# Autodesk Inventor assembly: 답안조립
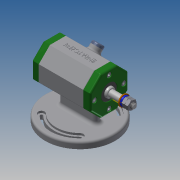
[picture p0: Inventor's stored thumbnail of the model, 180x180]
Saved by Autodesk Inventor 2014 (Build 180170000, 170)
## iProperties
Created: 2017-06
Part Number: 답안조립
Document SubType Name: Assembly
Designer: SCD-A14
Author: SCD-A14
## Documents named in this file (14)
- C:\Users\SCD-A14\Desktop\470607V1017\470607V1017\답안조립.iam
- C:\Users\SCD-A14\Desktop\470607V1017\470607V1017\V벨트풀리.ipt
- C:\Users\SCD-A14\Desktop\470607V1017\470607V1017\고무캡.ipt
- C:\Users\SCD-A14\Desktop\470607V1017\470607V1017\너트 M 8.ipt
- C:\Users\SCD-A14\Desktop\470607V1017\470607V1017\뒤커버.ipt
- C:\Users\SCD-A14\Desktop\470607V1017\470607V1017\베어링 15 x 32 x 9.ipt
- C:\Users\SCD-A14\Desktop\470607V1017\470607V1017\본체.ipt
- C:\Users\SCD-A14\Desktop\470607V1017\470607V1017\볼트 M4 x 12.ipt
- C:\Users\SCD-A14\Desktop\470607V1017\470607V1017\스프링와셔 8.ipt
- C:\Users\SCD-A14\Desktop\470607V1017\470607V1017\앞커버.ipt
- C:\Users\SCD-A14\Desktop\470607V1017\470607V1017\오일 실 15 25 7.ipt
- C:\Users\SCD-A14\Desktop\470607V1017\470607V1017\와셔 8x17.ipt
- C:\Users\SCD-A14\Desktop\470607V1017\470607V1017\축.ipt
- C:\Users\SCD-A14\Desktop\470607V1017\470607V1017\키 3 x 3 x 12.ipt
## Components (2 placed, 2 different names)
1. V벨트풀리:1
2. 고무캡:1
